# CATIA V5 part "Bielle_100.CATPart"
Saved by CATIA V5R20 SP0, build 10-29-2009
Part number: Manivelle.1
Bounding box of the stored display mesh (mm): x -20 to 20, y -65 to 65, z -15 to 15
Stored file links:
  D:\thinkmotion-MPB\Dropbox\IAO_2011\MMS_GR3\aweinling\aweinling\Bielle_100.CATPart
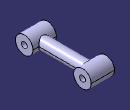
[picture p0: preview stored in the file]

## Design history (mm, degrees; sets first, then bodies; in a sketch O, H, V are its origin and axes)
Parameters
  `Longueur L` = 100 mm
  D_Trou = 10 mm
  D_Pivot = 30 mm
  D_Bielle = 20 mm
  `Largeur La` = 40 mm
Body1 (main body)
  Sketch1 on yz-plane, origin (0, 0, 0), H (0, 1, 0), V (0, 0, 1)
    circle A1 centre (50, 0) radius 15
    point P1 (50, 0)
    point P2 (-50, 0)
    circle A2 centre (-50, 0) radius 15
    radius A1 = 15 {= D_Pivot  /2}
    distance P2 P1 = 100 {= `Longueur L`}
    coincidence: P1 H
    symmetry: A1 A2 V
  Pad1: profile Sketch1, direction (1, 0, 0), length 20 {= `Largeur La` /2}, mirrored extent
  Sketch2 on zx-plane, origin (0, 0, 0), H (-1, 0, 0), V (0, 0, 1)
    circle A1 centre (0, 0) radius 10
    point P1 (10, 0)
    radius A1 = 10 {= D_Bielle /2}
    coincidence: P1 A1, P1 H
  Pad2: profile Sketch2, direction (0, 1, 0), length 50 {= `Longueur L` /2}, mirrored extent
  Sketch3 on end face of Pad1, origin (20, 96.2753, 0), H (0, 1, 0), V (0, 0, 1)
    point P1 (-46.2753, 0)
    reference projected circle E1 centre (-46.2753, 0) radius 15 from edge [face of Pad1 from Sketch1.A1 | end face of Pad1]
    concentricity: P1 E1
  Hole1: placed by Sketch3, at (20, 50, 0) direction (-1, 0, 0), diameter 10 {= D_Trou}, through (limit type 6)
  RectPattern1: of Hole1, direction 1 instances 2, spacing 100 {= `Longueur L`}, along axis of face of Pad2 from Sketch2.A1 reversed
